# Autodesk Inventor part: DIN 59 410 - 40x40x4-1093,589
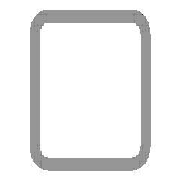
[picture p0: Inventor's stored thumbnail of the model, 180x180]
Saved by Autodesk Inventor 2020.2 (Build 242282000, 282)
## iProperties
Manager: www.cadconsulting.pl
Company: Fabian Stasiak CAD Consulting
IsCustomPart: 1
_CCFamilyMember: 20
_CCFamilyDisplayName: DIN 59410 (Kwadrat) - Rurki stalowe o przekroju kwadratowym formowane na gorąco
_FrameMemberDoc: Frame Member File
_Version: 15.0.0
_GetPNFromCC: 1
Created: 2015-01
Part Number: DIN 59 410 - 40x40x4-1093,589
Material: Stal, miękka
Description: Rurki stalowe o przekroju kwadratowym formowane na gorąco
Document SubType Name: Modellieren
Standard: DIN
Designer: F.Stasiak
Standards Organization: DIN
Language: pl-PL
Size Designation: 40x40x4
Categories: <MemberInstance><Categories><Category DisplayName="Kształtowniki konstrukcyjne" InternalName="089c4875-fa83-4c05-b084-43b9cc11f5ed" Mnemonic="GRDR"><CategoryPar
Stock Number: 40x40x4
Density: 7.85 g/cm^3
Appearance: Częściowo polerowana
Mass: 4423.13 g
Surface Area: 2832.4 cm^2
Volume: 563.456 cm^3
Catalog Web Link: www.expertbooks.pl
G_W: 40,000 mm
G_H: 40,000 mm
+CE7B5F3B-A732-4045-B8EB-16D64D143513+CUTDETAIL1: Wytnij
+7AB98C5A-503A-4884-8025-A18CEA999147+CUTDETAIL2: Wytnij
G_L: 1093,589 mm
Author: F.Stasiak
Subject: Zbiór ćwiczeń. Autodesk Inventor 2020. Kurs Professional
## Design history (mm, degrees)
node "Płaszczyzna początkowa"
node "Płaszczyzna końcowa"
sketch "Szkic1"
  geometry: L1 (-12, 20)-(12, 20); L2 (20, 12)-(20, -12); L3 (12, -20)-(-12, -20); L4 (-20, -12)-(-20, 12); L5 (-30.32, 0)-(30.32, 0) reference; L6 (0, -30.32)-(0, 30.32) reference; L7 (-12, 16)-(12, 16); L8 (16, 12)-(16, -12); L9 (12, -16)-(-12, -16); L10 (-16, -12)-(-16, 12); A1 r 8 centre (-12, 12) between (-12, 20) and (-20, 12); A2 r 8 centre (12, 12) between (20, 12) and (12, 20); A3 r 8 centre (12, -12) between (12, -20) and (20, -12); A4 r 8 centre (-12, -12) between (-20, -12) and (-12, -20); A5 r 4 centre (-12, 12) between (-12, 16) and (-16, 12); A6 r 4 centre (12, 12) between (16, 12) and (12, 16); A7 r 4 centre (12, -12) between (12, -16) and (16, -12); A8 r 4 centre (-12, -12) between (-16, -12) and (-12, -16); 3 further points
  constraints: 16 end point, 16 point on circle, 8 centre point, 8 tangent, 6 point on line, 4 parallel, 3 equal radius, 3 perpendicular, 1 horizontal, 7 other
  dimensions: "b" = 40 distance of point (-20, 20) point (20, 20); "msp_r" = 8 radius of A1 (= 2 x ParT); "d8" = 20 distance between parallel lines of L4 L6 (= d9); "d9" = 20 distance between parallel lines of L3 L5 (= 0.5 x b); "d10" = 4 distance between parallel lines of L3 L9 (= ParT)
extrude "Bryła" new body sketch "Szkic1" taper "d4" = 0 deg; stored distance "NLG" = 10
node "Driven Length"
  sketch "Sketch2"
    geometry: L1 (0, 0)-(10, 0) reference
    constraints: 2 end point, 1 horizontal
  workplane "Work Plane3"
  sketch "Sketch3"
    geometry: L1 (-2, 22.426)-(12, 22.426) reference; L2 (-2, 1116.016)-(12, 1116.016) reference
    dimensions: "d14" = 1093.5891 distance between parallel lines of L1 L2 (derived)
node "Płaszczyzna konstrukcyjna4"
feature "Podział1"
node "Płaszczyzna konstrukcyjna5"
feature "Podział2"
body "Solid1"
other parameters: "ParT" = 4, "G_OFFSET_START" = -22.42641 [user parameter; used in 1 equation term], "G_OFFSET_END" = -15.35534 [user parameter; used in 1 equation term], "d11" = 22.42641 (= -G_OFFSET_START), "d12" = 1116.01551 (= G_OFFSET_END + B_L), "G_L" = 1093.5891 (= d14) [user parameter], "B_L" = 1131.37085 [user parameter; used in 1 equation term], "d13" = 90 deg
